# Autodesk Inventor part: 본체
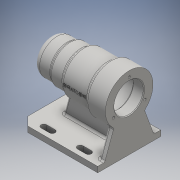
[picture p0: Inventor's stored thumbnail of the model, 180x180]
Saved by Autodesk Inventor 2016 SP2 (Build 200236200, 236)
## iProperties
Created: 2017-09
Part Number: 본체
Material: Generic
Document SubType Name: Modeling
Designer: Administrator
Density: 1 g/cm^3
Appearance: Default
Author: Administrator
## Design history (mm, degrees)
sketch "스케치1"
  geometry: L1 (-56, -45)-(56, -45); L2 (56, -45)-(56, 45); L3 (56, 45)-(-56, 45); L4 (-56, 45)-(-56, -45); L5 (-56, -45)-(56, 45); L6 (56, -45)-(-56, 45); 1 further point
  constraints: 12 end point, 2 midpoint, 2 parallel, 1 horizontal, 1 perpendicular
  dimensions: "d0" = 112 distance of L2.end L3.end; "d1" = 90 distance of L1.end L2.end
extrude "돌출1" new body sketch "스케치1" distance "d2" = 8; taper "d3" = 0 deg
chamfer "모따기1" distance "d4" = 12; stored, may be unused: second distance "d5" = 2, angle "d6" = 45 deg
sketch "스케치2"
  geometry: L1 (-56, 33)-(-44, 45) reference; L2 (-56, 33)-(-56, -33) reference; L3 (-44, -45)-(-56, -33) reference; L4 (-44, -45)-(56, -45) reference; L5 (56, -45)-(56, 45) reference; L6 (56, 45)-(-44, 45) reference; L7 (20, -38)-(32, -38); L8 (20, -30)-(32, -30); L9 (-20, -30)-(-32, -30); L10 (-32, -38)-(-20, -38); A1 r 4 centre (20, -34) between (20, -30) and (20, -38); A2 r 4 centre (32, -34) between (32, -38) and (32, -30); A3 r 4 centre (-20, -34) between (-20, -38) and (-20, -30); A4 r 4 centre (-32, -34) between (-32, -30) and (-32, -38); 1 further point
  constraints: 8 end point, 8 point on circle, 4 centre point, 4 horizontal, 4 tangent, 3 horizontal alignment
  dimensions: "d7" = 8 diameter of A1; "d8" = 8 diameter of A2; "d9" = 12 distance of A2.centre A1.centre; "d10" = 24 distance from line of A2.centre L5; "d11" = 34 vertical distance of A2.centre point (0, 0); "d12" = 8 diameter of A3; "d13" = 8 diameter of A4; "d14" = 12 distance of A4.centre A3.centre; "d15" = 40 distance of A3.centre A1.centre
extrude "돌출2" cut sketch "스케치2" stored distance "d16" = 8; taper "d17" = 0 deg
sketch "스케치3"
  geometry: L1 (-56, 70)-(56, 70); L2 (-56, 0)-(44, 0) reference; L3 (-56, 0)-(-56, 8) reference; L4 (-56, 70)-(-56, 104); L5 (-56, 104)-(-28, 104); L6 (-28, 104)-(-28, 100); L7 (-28, 100)-(11, 100); L8 (11, 100)-(11, 97); L9 (11, 97)-(31, 97); L10 (31, 97)-(31, 95); L11 (31, 95)-(56, 95); L12 (56, 95)-(56, 70); 2 further points
  constraints: 21 end point, 8 perpendicular, 1 horizontal, 1 midpoint, 1 point on line, 1 vertical
  dimensions: "d18" = 70 distance from line of L1 point (0, 0); "d19" = 68 diameter of L5 L1; "d20" = 60 diameter of L7 L1; "d21" = 54 diameter of L9 L1; "d22" = 50 diameter of L11 L1; "d23" = 25 distance from line of L10.end L12; "d24" = 45 distance between parallel lines of L8 L12; "d25" = 84 distance between parallel lines of L6 L12; "d26" = 112 distance between parallel lines of L12 L4
revolve "회전1" sketch "스케치3" stored, may be unused: angle "d27" = 90 deg
sketch "스케치4"
  geometry: L1 (0, 0)-(0, 90) reference; L2 (0, 90)-(-8, 90) reference; L3 (-8, 0)-(-8, 90) reference; L4 (0, 0)-(-8, 0) reference; L5 (-8, 80)-(-43.992, 66.9); L6 (-8, 10)-(-43.992, 23.1); A1 r 34 centre (-70, 45) between (-43.992, 66.9) and (-43.992, 23.1) reference; A2 r 34 centre (-70, 45) between (-43.992, 66.9) and (-43.992, 23.1) reference; 1 further point
  constraints: 4 end point, 4 point on circle, 2 point on line, 1 equal length
  dimensions: "d28" = 10 distance from line of L5.start L2; "d29" = 110 deg angle of L5 L3; "d30" = 110 deg angle of L6 L3
extrude "돌출3" join sketch "스케치4" distance "d31" = 8; taper "d32" = 0 deg
sketch "스케치5"
  geometry: L1 (31, 45)-(56, 45) reference; L2 (11, 43)-(31, 43) reference; L3 (31, 43)-(31, 97) reference; L4 (11, 40)-(11, 100) reference; L5 (-28, 40)-(11, 40) reference; L6 (-56, 8)-(44, 8) reference; L7 (56, 8)-(44, 8) reference; L8 (34, 8)-(24.622, 43); L9 (-28, 36)-(-28, 104) reference; L10 (-48, 36)-(-28, 36) reference; L11 (-48, 43.992)-(-48, 8) reference; 1 further point
  constraints: 2 end point, 2 point on line
  dimensions: "d33" = 22 distance of L8.start L7.start; "d34" = 105 deg angle of L8 L6
feature "리브1" sketch "스케치5" dims "d35" = 1, "d36" = 8, "d37" = 0, "d38" = 0, "d39" = 1, "d40" = 1
sketch "스케치6"
  geometry: L1 (0, 0)-(0, 90) reference; L2 (0, 90)-(-8, 90) reference; L3 (-8, 80)-(-8, 90) reference; L4 (-8, 80)-(-43.992, 66.9) reference; L5 (-43.992, 23.1)-(-8, 10) reference; L6 (-8, 0)-(-8, 10) reference; L7 (0, 0)-(-8, 0) reference; C1 r 21 at (-70, 45); A1 r 34 centre (-70, 45) between (-43.992, 66.9) and (-43.992, 23.1) reference; 1 further point
  constraints: 1 centre point, 1 coincident
  dimensions: "d41" = 42 diameter of C1
extrude "돌출4" cut sketch "스케치6" distance "d42" = 15; taper "d43" = 0 deg
sketch "스케치7"
  geometry: C1 r 21 at (0, 0) reference; C2 r 24 at (0, 0); 1 further point
  constraints: 1 centre point, 1 coincident
  dimensions: "d44" = 48 diameter of C2
extrude "돌출5" cut sketch "스케치7" distance "d45" = 54; taper "d46" = 0 deg
sketch "스케치8"
  geometry: C1 r 27 at (0, 0) reference; C2 r 21 at (0, 0); 1 further point
  constraints: 1 centre point, 1 coincident
  dimensions: "d47" = 42 diameter of C2
extrude "돌출6" cut sketch "스케치8" distance "d48" = 12; taper "d49" = 0 deg
sketch "스케치9"
  geometry: L1 (25, 49)-(25, 91) reference; L2 (25, 70)-(50, 70); L3 (25, 87.5)-(43, 87.5); L4 (43, 87.5)-(43, 86); L5 (43, 86)-(47, 86); L6 (47, 86)-(47, 80.5); L7 (47, 80.5)-(50, 80.5); L8 (50, 80.5)-(50, 70); 1 further point
  constraints: 15 end point, 5 perpendicular, 2 horizontal, 1 midpoint, 1 point on line
  dimensions: "d50" = 35 diameter of L3 L2; "d51" = 18 distance between parallel lines of L4 L1; "d52" = 32 diameter of L5 L2; "d53" = 4 distance of L4.end L5.end; "d54" = 21 diameter of L7 L2; "d55" = 3 distance of L6.end L7.end
revolve "회전2" sketch "스케치9" stored, may be unused: angle "d56" = 90 deg
sketch "스케치10"
  geometry: L1 (-70, 45)-(-96, 45); L2 (-70, 45)-(-57, 22.483); L3 (-70, 45)-(-57, 67.517); A1 r 34 centre (-70, 45) between (-43.992, 66.9) and (-43.992, 23.1) reference; A2 r 26 centre (-70, 45) between (-96, 45) and (-57, 22.483); 1 further point
  constraints: 6 end point, 3 point on circle, 1 centre point, 1 coincident, 1 horizontal, 1 horizontal alignment
  dimensions: "d57" = 52 diameter of A2; "d65" = 120 deg angle of L2 L1; "d66" = 120 deg angle of L3 L1
hole "구멍1" sketch "스케치10" at (-96, 45), (-57, 22.483), (-57, 67.517) diameter "d58" = 3.242; stored, may be unused: countersink angle "d62" = 90 deg, drill point angle "d64" = 118 deg; dims "d59" = 8, "d60" = 4, "d61" = 2, "d63" = 11
fillet "모깎기1" dims "d67" = 9
chamfer "모따기2" distance "d68" = 1; stored, may be unused: second distance "d69" = 2, angle "d70" = 45 deg
fillet "모깎기3" dims "d72" = 3
fillet "모깎기4" dims "d73" = 3
fillet "모깎기5" dims "d74" = 3
fillet "모깎기6" dims "d75" = 3
fillet "모깎기7" dims "d76" = 0.3
node "작업 평면1"
sketch "스케치12"
  geometry: L1 (-52.5, -70)-(47.5, -70) reference; L2 (47.5, 34)-(47.5, -26.008) reference; 2 further points
  constraints: 1 other
  dimensions: "d77" = 70 distance from line of point (-0.5, 0) L1; "d78" = 48 distance from line of point (-0.5, 0) L2
feature "엠보싱1" sketch "스케치12" dims "d0" = 112, "d1" = 90, "d7" = 8, "d8" = 8, "d9" = 12, "d10" = 24, "d11" = 34, "d12" = 8, "d13" = 8, "d14" = 12, "d15" = 40, "d79" = 0.5, "d80" = 0
fillet "모깎기8" dims "d81" = 3
fillet "모깎기9" dims "d82" = 3
fillet "모깎기10" dims "d83" = 3
fillet "모깎기11" dims "d84" = 3
fillet "모깎기12" dims "d85" = 3
node "솔리드1"
mirror "대칭1"
node "투영된 루프1"
node "투영된 루프2"
node "투영된 루프3"
node "투영된 루프4"
node "투영된 루프5"
